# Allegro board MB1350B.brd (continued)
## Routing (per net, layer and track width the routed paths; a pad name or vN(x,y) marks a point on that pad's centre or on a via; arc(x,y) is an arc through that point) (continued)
VDD: length 42.2
  TOP w0.254: U8.5 30.49,83.17 C29.2 ; U1.8 51.93,142.86 52.2,143.13 52.2,143.76 C12.2 ; U19.3 v1(43.43,24.19) ; U10.1 81.93,67.93 C40.2 ; U11.1 93.33,67.93 v1(93.6,68.2) ; U11.5 96.89,66.43 C43.2 ; U8.1 37.58,81.67 R42.2
  TOP w0.508: C43.2 v1(97.16,65.15) ; R13.2 v1(51.05,145.8) ; C40.2 v1(81.15,69.6) ; L1.1 v1(75.18,79.76) R84.2 ; v1(39.87,83.78) 39.84,83.78 R40.2 ; R106.1 v1(86.23,23.67) ; R56.2 v1(82.8,65.28) ; R109.2 v1(60.58,17.53) ; R57.2 v1(95,64.39) ; C12.2 v1(53.09,145.8) ; R14.1 v1(69.34,145.8) ; CN13.1 v1(86.11,76.71) ; C29.2 v1(30.48,84.2) ; R105.1 v1(42.93,21.97) ; R53.2 v1(101.85,71.37) ; R42.2 v1(37.59,80.77) ; R49.2 96.14,76.2 v1(96.14,75.76) ; T2.1 v1(93.09,56.96)
  BOTTOM w0.508: v1(95,64.39) 95,63.75 93.85,62.61 93.85,58.42 93.09,57.66 v1(93.09,56.96)
VDD_ADJ: length 15.2
  TOP w0.508: 64.08,55.5 C56.1 ; C56.1 64.9,56.25 ; C56.1 65.71,55.5 ; 53.92,65.53 TP6.1 ; TP6.1 54.86,66.47 ; TP6.1 55.8,65.53 ; TP6.1 54.86,64.59 ; R65.1 61.47,58.88 ; R65.1 61.47,57.71 ; R65.1 62.04,58.29 ; C55.1 63.12,56.12 ; C55.1 63.7,55.5 ; C55.1 62.53,55.5 ; 61.47,56.31 C53.2 ; C53.2 62.09,56.9 ; C53.2 61.47,57.48 ; 61.92,66.42 JP16.3 ; JP16.3 63.81,66.42 ; JP16.3 62.87,65.48 ; 61.68,55.54 U14.4 61.27,56.07
VDD_ANA: length 211.2
  TOP w0.254: 72.34,40.34 U17.1 71.87,40.63 72.14,40.89
  TOP w0.508: JP13.1 51.18,71.5 49.15,73.53 45.97,73.53 41.4,78.11 41.4,109.22 v1(38.86,111.76) ; RV3.1 100.08,9.27 C91.2 103.38,14.61 JP18.2 ; 72.69,40.64 C74.2 ; C74.2 73.28,41.26 ; C74.2 73.86,40.64 ; 75.31,40.08 C75.1 ; C75.1 75.31,41.71 ; C75.1 74.37,40.89 ; C75.1 76.25,40.89 ; R66.1 v1(69.72,60.07) ; v1(84.96,60.07) C50.2 83.89,60.13 U12.5 ; R74.2 v1(78.36,55.63)
  BOTTOM w0.508: CN4.16 38.86,121.67 v1(38.86,111.76) ; JP13.1 66.42,60.07 v1(69.72,60.07) v1(84.96,60.07) 85.47,59.56 85.47,57.66 83.44,55.63 v1(78.36,55.63) 76.71,53.98 v1(76.71,41.66) ; v1(76.71,40.51) 70.1,40.51 67.39,37.8 67.39,27.48 69.72,25.15 81.79,25.15 82.55,24.38 82.55,20.83 88.52,14.86 JP18.2
VDD_MCU: length 59.4
  TOP w0.254: U7.8 55,86.48 v1(55.37,86.11)
  TOP w0.508: v1(68.96,92.33) 68.96,90.68 65.28,87 v1(65.28,86.61) 65.28,83.69 C31.1 68.71,83.44 69.34,84.07 JP11.1 ; SB13.2 52.83,104.9 v1(54.36,103.38)
  BOTTOM w0.508: v1(68.96,92.33) 68.45,92.33 59.69,101.09 56.64,101.09 v1(54.36,103.38) ; C32.2 C33.1 54.86,87.63 54.86,86.61 v1(55.37,86.11) 61.47,86.11 61.98,86.61 v1(65.28,86.61)
VDD_PG: length 2.6
  TOP w0.381: U14.3 61.27,51.63 R79.2
AIN_1: length 7.7
  TOP w0.127: R15.2 R14.2 68.83,143 67.82,141.99 67.82,138.68 67.54,138.4 U2.10
BOOTLOADER_BOOT0: length 67.3
  TOP w0.127: v1(65.53,88.9) 64.52,87.88 64.52,68.71 63.63,67.82 52.7,67.82 50.8,65.91 50.8,58.17 49.28,56.64 44.2,56.64 43.49,57.34 U13.20 ; D4.1 77.49,87.5 v1(78.23,87.5)
  BOTTOM w0.127: v1(65.53,88.9) 65.91,88.9 67.31,87.5 v1(78.23,87.5)
BOOTLOADER_RESET: length 18.5
  TOP w0.127: v1(44.81,55.98) SB28.2 44.79,54.74 U13.16
  BOTTOM w0.127: JP12.2 42.93,67.56 42.93,57.15 44.07,56.01 44.78,56.01 v1(44.81,55.98)
E5V: length 112.5
  TOP w0.508: L2.3 5.27,42.12 ; L2.3 4.1,43.29 ; L2.3 2.93,42.12 ; L2.3 4.1,40.96 ; 15.88,41.35 C70.1 ; C70.1 13.16,43.05 ; C70.1 15.88,44.76
  TOP w0.762: D10.1 40.53,114.94 34.92,114.94 24.26,104.27 24.26,89.03 23.09,87.86 21.74,87.86 20.98,87.1 20.98,83.31 20.5,82.83 15.82,82.83 v1(13.94,80.95) v1(13.94,79.98) ; 14.88,46.41 14.88,47.09 14.5,47.47 12.19,47.47 11.51,48.16 v1(11.51,50.6) 11.51,50.75 v1(12.19,51.44)
  TOP w1.016: JP17.6 5.33,45.21 5.46,45.09
  BOTTOM w0.762: v1(11.51,50.6) 11.51,50.77 12.17,51.44 v1(12.19,51.44) 12.75,51.44 14.55,53.24 14.55,62.05 13.94,62.66 v1(13.94,79.98) v1(13.94,80.95)
EXT_I2C_PWR: length 167.5
  TOP w0.508: CN2.5 9.64,151.5 8.89,150.75 R12.2 v1(9.91,146.56)
  BOTTOM w0.508: CN5.17 102.11,125.48 102.11,163.83 95.33,170.61 24.69,170.61 22.99,168.91 22.99,150.88 18.67,146.56 v1(9.91,146.56)
I2C_PU: length 49
  TOP w0.127: R9.2 R10.2 16.51,153.92 v1(26.42,153.92)
  BOTTOM w0.127: CN4.17 36.32,122.17 34.8,123.7 34.8,131.88 30.35,136.32 30.35,149.99 v1(26.42,153.92)
LED_STLINK: length 69.4
  TOP w0.127: v1(28.42,138.84) 29.21,138.05 51.69,138.05 52.84,136.9 U2.30 ; v1(11.43,113.49) 11.43,109.98 R35.1 R36.1
  BOTTOM w0.127: v1(28.42,138.84) 28.42,131.17 11.43,114.17 v1(11.43,113.49)
NETB2_2: length 18.5
  TOP w0.127: B2.3 66.87,9.97 66.55,10.29 C89.2 63.4,14.73 D9.1 60.6,14.71 R109.1 SB42.2 59.05,10.04 B2.2
NETB3_1: length 22.9
  TOP w0.127: B3.1 75.62,7.63 75.62,9.86 77.85,12.09 79.5,12.09 80.92,13.51 80.92,14.33 80.71,14.54 D8.4 80.03,14.54 79.73,14.25 v1(79.73,13.64) ; SB39.2 C85.2 v1(78.49,19.43)
  BOTTOM w0.127: v1(78.49,19.43) 78.49,14.88 v1(79.73,13.64)
NETB3_2: length 25
  TOP w0.127: B3.2 77.5,5.11 76.1,5.11 74.85,6.35 74.85,10.13 77.44,12.73 78.56,12.73 79.1,13.26 79.1,15.7 78.35,16.44 D8.1 76.14,16.44 75.31,17.27 C84.2 SB38.2
NETB3_3: length 28.8
  TOP w0.127: B3.3 78.48,4.11 76,4.11 74.12,5.99 74.12,10.31 77.14,13.34 78.26,13.34 78.51,13.59 78.51,14.33 78.29,14.54 D8.3 75.85,14.54 72.14,18.26 C83.2 SB37.2
NETB3_4: length 20.9
  TOP w0.127: SB40.2 C86.2 81.66,19.94 79.15,17.42 79.15,16.26 79.91,15.49 D8.5 80.75,15.49 81.53,14.71 81.53,13.03 79.4,10.9 79.4,10.11 81.61,7.9 82.27,7.9 B3.4
NETB3_5: length 12.8
  TOP w0.127: B3.5 86.23,13.84 R106.2
NETB3_6: length 15.8
  TOP w0.127: SB41.2 C87.2 84.71,20.19 83.82,19.3 82.22,19.3 80.32,17.41 D8.6 80.76,16.44 82.12,15.09 82.12,11.71 B3.6
NETBT1_1: length 29.6
  TOP w0.508: BT1.1 v1(50.62,39.83)
  BOTTOM w0.508: v1(50.62,39.83) 50.62,63.42 JP15.3
NETC5_2: length 55.2
  TOP w0.127: R1.1 R2.2 C5.2 v1(57.02,158.75)
  BOTTOM w0.127: v1(57.02,158.75) 58.42,160.15 58.42,167.64 57.2,168.86 31.57,168.86 25.91,163.19 25.91,158.5 JP3.1
NETC6_2: length 52.2
  TOP w0.127: v1(60.45,157.99) C6.2 R3.2
  BOTTOM w0.127: v1(60.45,157.99) 60.96,158.5 60.96,167.51 59.13,169.34 31.29,169.34 JP2.2
NETC10_2: length 61.7
  TOP w0.127: v1(72.52,158.75) R7.2 R8.2 C10.2
  BOTTOM w0.127: v1(72.52,158.75) 71.12,160.15 71.12,167.77 69.01,169.88 26.49,169.88 JP1.2
NETC11_2: length 1.8
  TOP w0.127: C11.2 SB1.1
NETC24_2: length 2.3
  TOP w0.508: C24.2 47.3,123.5 U4.4
NETC26_2: length 13.1
  TOP w0.508: 47.8,118.94 U4.3 47.3,118.19 ; D10.2 43.29,116.03 ; D10.2 43.87,115.44 ; D10.2 42.7,115.44 ; D10.2 43.29,114.86 ; D3.2 43.29,114 ; D3.2 43.87,113.41 ; D3.2 42.7,113.41 ; D3.2 43.29,112.83 ; D2.2 43.87,117.47 ; D2.2 43.29,118.06 ; D2.2 42.7,117.47 ; D2.2 43.29,116.89 ; C26.2 45.47,117.84 ; C26.2 44.88,117.22 ; C26.2 46.05,117.22 ; C27.2 47.57,117.22 ; C27.2 46.99,117.84 ; C27.2 46.41,117.22 ; 45.41,118.19 U4.1 44.91,118.94
NETC34_1: length 4.3
  TOP w0.127: R43.1 50.42,80.01 C34.1 49.78,77.6 X2.2
NETC35_1: length 4.4
  TOP w0.127: X2.1 50.93,77.73 50.93,79.12 C35.1 51.69,79.88 R44.1
NETC36_1: length 4.4
  TOP w0.127: X3.2 58.8,77.1 C36.1 58.93,79.5 R45.1
NETC37_1: length 4.4
  TOP w0.127: R46.1 60.2,79.5 C37.1 60.33,77.1 X3.1
NETC44_1: length 4.4
  TOP w0.127: U13.3 33.89,61.24 33.25,60.6 32.11,60.6 C44.1
NETC45_1: length 2.6
  TOP w0.127: U13.1 33.09,62.54 C45.1
NETC45_2: length 2.6
  TOP w0.127: U13.2 33.27,61.89 C45.2
NETC46_1: length 6.6
  TOP w0.508: TP9.1 C46.1 R62.1 R61.2
NETC47_1: length 10.1
  TOP w0.254: U12.4 82.48,58.23 83.31,57.4 R70.1 83.31,55.09 RV1.1
  TOP w0.508: U12.4 81.59,58.23 80.9,58.93 80.9,60.83 81.28,61.21 C47.1 R59.2
NETC47_2: length 5
  TOP w0.508: R62.2 79.64,60.07 U12.1 79.76,60.19 C47.2 R59.1
NETC48_1: length 2.7
  TOP w0.127: U13.27 44.82,61.89 C48.1
NETC49_1: length 4.7
  TOP w0.127: C49.1 45.31,59.46 44.04,59.46 43.56,59.94 U13.24
NETC49_2: length 4.5
  TOP w0.127: C49.2 45.57,62.76 43.15,62.76 42.93,62.54 U13.28
NETC51_1: length 5.1
  TOP w0.254: C51.1 C54.1 75.44,55.88 R72.1 R73.1
NETC51_2: length 13.4
  TOP w0.508: TP8.1 72.9,59.94 R68.2 75.31,59.05 76.83,59.05 C51.2 79.63,58.17 U12.3
NETC53_1: length 4.6
  TOP w0.381: U14.5 60.33,56.52 C53.1
  TOP w0.508: R64.1 R65.2 C53.1
NETC58_1: length 11.8
  TOP w0.254: RV1.2 85.35,51.98 RV1.3 84.84,55.35 R70.2 87.5,56.77 88.27,56.01 C58.1
NETC59_1: length 5.8
  TOP w0.254: R67.1 R66.2 R69.1 71.25,54.86 C59.1
NETC60_1: length 4.2
  TOP w0.254: C60.1 72.9,54.74 R67.2 R68.1
NETC61_1: length 3.9
  TOP w0.254: C61.1 79.12,53.21 R74.1 R73.2
NETC62_1: length 3.9
  TOP w0.381: C62.1 59.38,50.61 U14.1
  TOP w0.508: R80.1 C62.1
NETC63_1: length 7.5
  TOP w0.127: SB30.2 51.21,50.57 50.83,50.19 47.14,50.19 R82.1 C63.1
NETC63_2: length 63.4
  TOP w0.127: CN11.4 14.71,74.7 17.78,71.63 17.78,66.67 19.11,65.35 24.06,65.35 26.48,62.92 26.48,59.37 28.96,56.9 28.96,49.1 31.83,46.23 37.72,46.23 40.41,48.92 U15.6 42.82,48.92 C63.2 44.48,50.57 47.9,50.57 48.03,50.7 SB29.2 SB30.1
NETC65_2: length 75.7
  TOP w0.127: C65.2 69.85,49.3 68.22,50.93 68.22,65.71 78.44,75.92 78.44,82.73 74.75,86.41 73.23,86.41 70.36,89.28 70.36,94.16 72.86,96.66 76.24,96.66 79.63,100.05 JP19.1
  TOP w0.381: C66.1 C65.2
NETC66_2: length 1.5
  TOP w0.381: R89.1 C66.2
NETC67_1: length 4.7
  TOP w0.508: U16.5 C67.1 R88.2 R87.1
NETC68_1: length 11.4
  TOP w0.254: U17.2 71.37,40.89 C73.2
  TOP w0.381: C68.1 73.41,44.45 R90.2 C73.2
NETC68_2: length 19.7
  TOP w0.381: CN15.6 100.96,46.1 R86.2 96.14,46.1 94.23,44.2 94.23,42.29 92.9,40.95 D6.6 89.14,44.45 C68.2
NETC69_1: length 2.7
  TOP w0.254: C69.1 70.37,41.01 U17.4
NETC73_1: length 5.6
  TOP w0.254: C73.1 70.87,41.91 U17.3
  TOP w0.381: R89.2 R90.1 C73.1
NETC76_1: length 5.1
  TOP w0.254: U17.7 71.37,36.83 C76.1
  TOP w0.381: R95.2 R94.1 C76.1
NETC76_2: length 11.3
  TOP w0.254: U17.8 71.87,38.19 71.88,38.18 71.88,37.34 C76.2
  TOP w0.381: C77.1 77.09,35.56 76.45,34.92 R94.2 C76.2
NETC77_2: length 24.4
  TOP w0.381: C77.2 88.77,35.56 92.27,39.06 D6.4 94.29,39.06 95.63,37.72 R92.2 108.36,37.72 CN15.4
NETC78_2: length 4
  TOP w0.381: C80.1 70.36,32.77 69.98,32.77 C78.2 R93.2
NETC79_1: length 18.3
  TOP w0.508: D7.1 15.23,35.88 ; D7.1 15.23,34.73 ; D7.1 15.69,35.31 ; 15.11,29.96 U18.3 ; U18.3 15.76,30.45 ; U18.3 15.11,30.93 ; 15.24,31.93 C79.1 ; C79.1 15.24,33.1 ; C79.1 15.86,32.51
  TOP w1.143: 15.62,38.1 13.97,39.75 9.14,39.75 6.52,37.12 L2.1
NETC79_2: length 23.5
  TOP w0.508: 9.4,38.35 9.1,38.06 L2.2 ; CN16.2 7.54,23.12 ; CN16.2 9.83,21.92 ; CN16.2 7.54,20.73 ; CN16.2 5.26,21.92 ; CN16.3 5.64,26.92 ; CN16.3 4.45,24.64 ; CN16.3 4.45,29.21 ; CN16.3 3.25,26.92 ; C79.2 13.72,33.1 ; C79.2 13.09,32.51 ; C79.2 13.72,31.93 ; L2.2 10.27,37.12 ; L2.2 8.17,37.12 7.87,36.83 ; L2.2 9.1,35.95 ; D7.2 13.98,35.88 ; D7.2 13.98,34.73 ; D7.2 13.52,35.31 ; 13.19,30.45 U18.2 13.84,30.93
NETC80_2: length 1.4
  TOP w0.381: C80.2 R95.1
NETC81_1: length 10.2
  TOP w0.508: L3.2 89.79,29.34 C82.1 92.33,28.96 C81.1 95.5,30.48 CN14.13 CN14.14
NETC81_2: length 10
  TOP w0.508: L4.2 91.82,26.42 C82.2 92.84,27.43 C81.2 96.01,27.43 CN14.15 CN14.16
NETC89_1: length 1.7
  TOP w0.127: C89.1 R110.2
NETC90_2: length 3.2
  TOP w0.127: SB43.2 C90.2 R111.1
NETC93_1: length 3.9
  TOP w0.381: C93.1 59.38,26.99 U21.1
  TOP w0.508: C93.1 R115.1
NETC94_1: length 4.7
  TOP w0.508: U21.5 C94.1 R116.2 R117.1
NETCN1_1: length 42.8
  TOP w0.127: CN1.1 87.63,167.94 86.41,169.16 57.4,169.16 55.93,167.69 55.93,161.59 54.86,160.53 R2.1
NETCN1_14: length 4.9
  TOP w0.127: CN1.14 72.39,160.4 R7.1
NETCN1_15: length 7.8
  TOP w0.127: CN1.15 70.87,165.61 70.87,162.69 71.63,161.93 R6.2
NETCN1_17: length 7.7
  TOP w0.127: CN1.17 68.58,165.35 68.58,162.69 68.83,162.43 R5.2
NETCN1_19: length 7.6
  TOP w0.127: CN1.19 65.91,165.48 R4.2
NETCN1_26: length 4.8
  TOP w0.127: R3.1 57.78,163.45 CN1.26
NETCN4_6: length 3.6
  TOP w0.127: R11.2 CN4.6
NETCN6_4: length 3.9
  TOP w0.127: R19.1 5.73,134.86 CN6.4
NETCN8_2: length 8.3
  TOP w0.127: U6.13 95.18,103.56 95,103.38 94.49,103.38 v1(93.92,103.95) ; v1(97.54,101.73) 99.07,101.73 CN8.2
  BOTTOM w0.127: v1(93.92,103.95) 94.49,103.38 95.63,103.38 97.28,101.73 v1(97.54,101.73)
NETCN8_3: length 5.7
  TOP w0.127: CN8.3 v1(97.54,102.99) ; v1(94.74,103.96) U6.12
  BOTTOM w0.127: v1(94.74,103.96) 95.69,103.96 96.52,103.12 97.41,103.12 97.54,103 v1(97.54,102.99)
NETCN8_5: length 11.5
  TOP w0.127: CN8.5 v1(100.68,105.19) ; U6.11 95.16,104.36 94.87,104.65 94.49,104.65 v1(93.98,105.16)
  BOTTOM w0.127: v1(100.68,105.19) 99.44,106.43 97.03,106.43 95.25,104.65 94.49,104.65 v1(93.98,105.16)
NETCN8_7: length 9.4
  TOP w0.127: v1(100.71,107.39) CN8.7 ; U6.10 95.36,104.76 94.97,105.16 v1(94.74,105.16)
  BOTTOM w0.127: v1(100.71,107.39) 99.13,107.39 98.55,106.81 96.77,106.81 95.12,105.16 v1(94.74,105.16)
NETCN8_10: length 26.1
  TOP w0.127: SB8.2 109.73,110.84 CN8.10 109.43,103.33 107.31,101.22 102.11,101.22 100.84,99.95 98.04,99.95 97.03,100.97 97.03,102.23 96.9,102.36 U6.1
NETCN9_18: length 36.3
  TOP w0.127: SB19.1 53.72,81.66 53.72,83.31 52.83,84.2 v1(52.83,85.34)
  BOTTOM w0.127: CN9.18 51.56,86.61 v1(52.83,85.34)
NETCN9_19: length 32.5
  TOP w0.127: SB18.2 v1(47.5,80.9)
  BOTTOM w0.127: v1(47.5,80.9) 43.18,85.22 29.21,85.22 28.32,86.11 23.75,86.11 22.86,85.22 20.83,85.22 CN9.19
NETCN9_21: length 29.8
  TOP w0.127: R47.1 v1(45.21,80.64)
  BOTTOM w0.127: v1(45.21,80.64) 43.05,82.8 28.96,82.8 27.05,84.71 24.38,84.71 22.48,82.8 20.95,82.8 CN9.21
NETCN10_13: length 33.4
  TOP w0.127: v1(60.96,85.22) 61.59,84.58 SB21.2
  BOTTOM w0.127: v1(60.96,85.22) 62.23,85.22 62.99,85.98 66.04,85.98 66.42,85.6 79.6,85.6 85.7,91.69 CN10.13
NETCN10_15: length 36.3
  TOP w0.127: v1(58.8,84.85) 57.53,83.58 SB20.2
  BOTTOM w0.127: v1(58.8,84.85) 58.92,84.85 59.05,84.71 65.53,84.71 67.94,82.3 79.25,82.3 86.11,89.15 CN10.15
NETCN10_18: length 9.7
  TOP w0.127: R41.2 88.77,82.93 89.53,83.69 89.53,85.34 CN10.18
NETCN10_19: length 15.4
  TOP w0.127: R39.1 77.47,85.22 85.47,85.22 86.61,84.07 CN10.19
NETCN10_20: length 7.6
  BOTTOM w0.127: CN10.20 89.79,83.06 83.82,83.06 SB44.1
NETCN10_22: length 8.1
  BOTTOM w0.127: CN10.22 89.66,82.68 87.38,82.68 86.11,81.41 SB45.1
NETCN11_2: length 37.6
  TOP w0.127: U13.6 34.09,59.29 34.07,59.27 30.81,59.27 29.11,60.97 29.11,67.79 22.35,74.55 17.53,74.55 11.84,80.24 CN11.2
NETCN11_3: length 37.6
  TOP w0.127: U13.10 30.89,56.69 27.57,60.01 27.57,67.05 21.46,73.15 16.89,73.15 12.57,77.47 CN11.3
NETCN11_6: length 40.7
  TOP w0.127: CN11.6 11.07,81.64 17.53,75.18 22.48,75.18 29.68,67.98 29.68,61.12 30.89,59.92 34.07,59.92 34.09,59.94 U13.5
NETCN11_7: length 40.6
  TOP w0.127: CN11.7 7.75,78.61 12.19,78.61 17.14,73.66 21.72,73.66 28.09,67.28 28.09,60.38 31.12,57.34 U13.9
NETCN11_8: length 46.4
  TOP w0.127: U13.7 34.09,58.64 34.07,58.62 30.61,58.62 28.6,60.62 28.6,67.54 22.1,74.04 17.4,74.04 12.45,78.99 9.4,78.99 8.13,80.26 6.86,80.26 6.1,79.5 6.1,77.5 CN11.8
NETCN11_9: length 69.8
  TOP w0.127: SB32.2 SB31.2 48.03,46.76 47.65,46.38 42.6,46.38 v1(42.57,46.35) 38.61,46.35 37.97,45.72 31.5,45.72 28.45,48.77 28.45,56.64 26.04,59.05 26.04,62.74 23.88,64.9 18.92,64.9 17.14,66.67 17.14,71.5 15.32,73.33 CN11.9 ; v1(42.57,50.19) U15.7
  BOTTOM w0.127: v1(42.57,46.35) v1(42.57,50.19)
NETCN12_7: length 19.4
  TOP w0.127: CN13.2 94.87,76.71 R49.1 R48.1 95,78.99 95.58,79.58 101.82,79.58 U9.3 107.27,78.12 108.01,78.87
NETCN12_9: length 17.3
  TOP w0.127: CN12.9 107.52,76.82 U9.1 102.88,76.82 102.49,77.22 99.95,77.22 97.66,74.93 R51.2 R50.1 94.49,75.44 CN13.4
NETCN12_11: length 6.1
  TOP w0.127: 108.01,73.79 103.5,73.79 R52.2 R53.1
NETCN12_15: length 27.8
  TOP w0.127: CN13.10 94.87,71.63 R54.1 96.01,72.52 97.79,72.52 98.81,73.53 98.81,75.31 100.32,76.82 U9.5 101.74,76.82 103.38,75.18 108.71,75.18 109.35,74.55 109.35,70.04 CN12.15
NETCN12_17: length 4.3
  TOP w0.127: R55.2 CN12.17
NETCN12_19: length 4.3
  TOP w0.127: R58.2 108.01,63.63
NETCN14_1: length 4.6
  TOP w0.254: 93.73,60.07 R60.1 95.89,61.59 CN14.1
NETCN14_3: length 2.8
  TOP w0.254: R63.1 CN14.3
NETCN14_7: length 3.3
  TOP w0.127: CN14.7 95.38,52.2 R76.2
NETCN14_8: length 8.7
  TOP w0.127: T2.3 94.19,55.08 93.73,54.61 R75.1 94.23,53.59 95,54.36 98.04,54.36 CN14.8
NETCN15_2: length 55.9
  TOP w0.254: v1(89.41,48.13) 88.61,48.13 87.59,49.15 76.43,49.15 75.44,50.14 R72.2 ; CN15.2 v1(113.25,47.66) ; D6.1 v1(88.83,40.95)
  BOTTOM w0.254: v1(113.25,47.66) 111.3,45.72 100.33,45.72 95.56,40.95 v1(88.83,40.95) 88.52,41.27 88.52,47.24 v1(89.41,48.13)
NETCN16_1: length 10.5
  TOP w0.508: CN16.1 11.84,26.92 ; CN16.1 10.64,29.21 ; CN16.1 10.64,24.64 ; CN16.1 9.45,26.92 ; U18.1 14.48,27.44 ; U18.1 15.76,26.96 ; U18.1 13.19,26.96 ; U18.1 14.48,26.47
NETCN17_1: length 14.9
  TOP w0.127: R111.2 R112.1 95.5,17.78 96.27,18.54 105.41,18.54 CN17.1
NETD1_2: length 2.6
  TOP w0.127: R28.1 65.77,124.1 D1.2
NETD4_2: length 2.9
  TOP w0.127: D4.2 JP9.3
NETD5_2: length 24.5
  TOP w0.127: D5.2 58.66,70.23 42.8,70.23 JP12.1
NETJP4_2: length 65.4
  TOP w0.127: R61.1 74.55,71.04 79.12,75.62 79.12,82.83 74.83,87.12 73.41,87.12 70.87,89.66 70.87,93.98 72.73,95.85 76.87,95.85 80.85,99.82 80.85,107.14 80.31,107.67 76.17,107.67 JP4.2
NETJP5_2: length 90
  TOP w0.127: R27.1 62.74,126.36 62.23,125.86 62.23,124.97 61.47,124.21 50.8,124.21 44.7,130.3 31.37,130.3 v1(30.86,129.79) ; R27.1 62.23,127.51 62.23,129.79 60.73,131.29 U2.39 ; R27.1 R28.2
  BOTTOM w0.127: v1(30.86,129.79) 31.59,129.06 31.59,112.49 28.7,109.6 18.41,109.6 12.06,103.25 JP5.2
NETJP6_2: length 74.1
  TOP w0.127: R93.1 67.56,38.35 67.56,66.14 77.75,76.33 77.75,82.3 74.3,85.75 73.1,85.75 69.82,89.03 69.82,94.34 74.55,99.06 JP6.2
NETJP8_2: length 39.4
  BOTTOM w0.127: JP14.2 17.86,70.79 17.86,91.82 19.2,93.17 29.92,93.17 JP8.2
NETJP10_2: length 13.7
  TOP w0.127: JP10.2 34.54,88.14 34.54,82.8 35.17,82.17 U8.2 36.71,82.17 36.83,82.3 38.48,82.3 R42.1
NETJP11_2: length 3.3
  TOP w0.508: R84.1 JP11.2
NETJP14_1: length 33.1
  TOP w0.127: U13.17 v1(40.64,55.39) ; v1(26.42,64.77) JP14.1
  BOTTOM w0.127: v1(40.64,55.39) 29.19,55.39 26.42,58.17 v1(26.42,64.77)
NETJP14_3: length 39.3
  TOP w0.127: U15.1 37.57,51.46 37.85,51.18 37.85,47.24 37.34,46.74 32,46.74 29.46,49.28 29.46,57.18 26.95,59.69 26.95,63.22 23.75,66.42 JP14.3
NETJP18_1: length 57.8
  TOP w0.127: R108.1 99.82,17.4 JP18.1 ; v1(70.23,37.34) 70.87,37.98 U17.6
  BOTTOM w0.127: JP18.1 100.43,17.4 99.54,16.51 87.76,16.51 83.19,21.08 83.19,24.89 82.17,25.91 71.37,25.91 70.03,27.25 70.03,37.13 v1(70.23,37.34)
NETL3_1: length 4.1
  TOP w0.508: R100.2 R96.2 86.74,28.07 L3.1
NETLD1_2: length 19.7
  TOP w0.127: LD1.2 19.94,10.79 29.72,20.57 R104.2
NETLD2_2: length 19.7
  TOP w0.127: R103.2 28.07,20.32 18.16,10.41 LD2.2
NETLD3_2: length 19.8
  TOP w0.127: R102.2 26.42,20.19 16.38,10.16 LD3.2
NETLD4_2: length 19.8
  TOP w0.127: R101.2 24.77,19.94 14.61,9.78 LD4.2
NETLD5_1: length 1.5
  TOP w0.127: R33.2 LD5.1
NETLD5_2: length 23.8
  TOP w0.127: v1(10.72,111.76) 9.68,110.72 6.5,110.72 LD5.2 ; U5.3 22.87,120.65 R31.2 v1(20.95,121.79)
  BOTTOM w0.127: v1(20.95,121.79) 20.75,121.79 v1(10.72,111.76)
NETLD6_2: length 3.6
  TOP w0.127: LD6.2 8.09,108.17 R35.2
NETLD6_3: length 3.6
  TOP w0.127: LD6.3 7.99,106.67 R36.2
NETLD6_4: length 6.8
  TOP w0.127: R37.1 8.51,105.66 3.46,105.66 LD6.4
NETLD7_1: length 1.8
  TOP w0.508: R71.1 LD7.1
NETLD8_2: length 1.5
  TOP w0.127: LD8.2 R83.1
NETR13_1: length 5.9
  TOP w0.127: R13.1 49.53,143.41 51.08,141.86 U1.6 52.83,141.86 SB5.1
NETR16_2: length 2.6
  TOP w0.127: R16.2 61.47,142.91 61.73,142.65 U2.20
NETR18_2: length 1.7
  TOP w0.127: T1.2 11.68,131.68 R18.2
NETR20_2: length 4.6
  TOP w0.127: T1.1 13.4,129.73 R20.2 R21.1 R22.1
NETR23_2: length 2.4
  TOP w0.127: U2.44 63.23,130.06 R23.2
NETR24_2: length 6.7
  TOP w0.127: R24.2 68.71,131.95 68.71,133.6 67.91,134.4 U2.2
NETR25_2: length 7.1
  TOP w0.127: U2.3 68.04,134.9 69.22,133.73 69.22,131.06 R25.2
NETR34_1: length 8.6
  TOP w0.127: U6.4 96.77,103.5 97.92,103.5 98.17,103.76 98.17,107.57 97.66,108.08 97.28,108.08 SB9.2 R34.1
NETR38_1: length 4.4
  TOP w0.127: R38.1 49.34,94.23 U7.57
NETR40_1: length 3.9
  TOP w0.127: U8.3 36.19,82.67 36.58,83.06 R40.1 SB16.2
NETR56_1: length 4.2
  TOP w0.127: SB26.2 R56.1 85.34,66.29 85.48,66.43 U10.5
NETR57_1: length 5.6
  TOP w0.127: R57.1 94.23,66.04 94.23,67.06 93.86,67.43 U11.2 91.82,67.43 SB25.2
NETR64_2: length 68
  TOP w0.127: RV2.1 39.37,18.8 48.13,18.8 49.91,20.57 49.91,29.21 53.59,32.89 53.59,57.28 54.61,58.29 R64.2
NETR76_1: length 63.8
  TOP w0.127: SB12.2 97.41,106.43 97.41,106.05 v1(97.17,105.8) 97.17,104.91 97.01,104.76 U6.7 ; v1(91.31,52.2) R76.1 R78.2
  BOTTOM w0.127: v1(97.17,105.8) 97.17,105.02 97.46,104.73 98.6,104.73 99.54,103.78 99.54,70.84 98.04,69.34 98.04,68.45 96.65,67.06 96.65,63.75 95,62.1 95,57.66 92.33,54.99 92.33,53.21 v1(91.31,52.2)
NETR77_1: length 1.5
  TOP w0.127: R77.1 SB29.1
NETR82_2: length 4.8
  TOP w0.127: R82.2 50.7,49.56 51.21,49.05 SB32.1
NETR83_2: length 45
  TOP w0.127: R83.2 v1(16,48.51) ; v1(40.51,25.49) U19.1
  BOTTOM w0.127: v1(40.51,25.49) 35.6,25.49 28.19,32.89 28.19,47.12 26.8,48.51 v1(16,48.51)
NETR85_1: length 1.5
  TOP w0.127: SB31.1 R85.1
NETR97_1: length 1.9
  TOP w0.127: R98.1 R97.1
NETR97_2: length 5.6
  TOP w0.127: R97.2 R99.1 43.94,25.27 43.51,24.84 U19.2
NETR101_1: length 1.4
  TOP w0.127: R101.1 SB33.1
NETR102_1: length 1.4
  TOP w0.127: R102.1 SB34.1
NETR103_1: length 1.4
  TOP w0.127: SB35.1 R103.1
NETR104_1: length 1.4
  TOP w0.127: SB36.1 R104.1
NETR105_2: length 4.3
  TOP w0.127: R105.2 45.59,23.88 45.9,24.19 U19.6
NETR107_2: length 4.8
  TOP w0.127: R107.2 47.12,20.57 47.83,21.29 U19.5
NETR112_2: length 1.5
  TOP w0.127: R113.1 R112.2
NETR113_2: length 8.9
  TOP w0.127: R113.2 RV3.2
NETSB4_1: length 1.9
  TOP w0.127: U1.7 52.7,142.36 SB4.1
NETSB10_1: length 7.3
  TOP w0.127: SB10.1 SB13.1 55,104.9 U7.41
NETSB11_1: length 7.3
  TOP w0.127: SB11.1 SB14.1 55.49,105.02 U7.40
NETSB15_1: length 1.7
  TOP w0.127: U6.16 95.56,100.77 SB15.1
NETSB24_2: length 1.9
  TOP w0.127: SB24.2 81.4,67.43 U10.2
NETTP2_1: length 77.5
  TOP w0.127: U2.21 61.23,142.22 60.58,142.88 60.58,146.05 58.04,148.59 47.62,148.59 39.88,140.84 29.57,140.84 v1(27.58,138.86)
  BOTTOM w0.127: TP2.1 27.58,131.24 v1(27.58,138.86)
OSC_IN: length 7.8
  TOP w0.127: U2.5 68.57,135.9 C19.1 69.85,135.89 73.02,135.89 X1.2
OSC_OUT: length 7.5
  TOP w0.127: U2.6 68.84,136.4 C18.1 69.98,137.54 73.67,137.54 X1.1
PA0: length 122.7
  TOP w0.127: v1(74.42,26.42) 73.79,25.78 SB38.1 ; v1(62.48,90.17) 61.92,90.74 U7.17
  BOTTOM w0.127: v1(74.42,26.42) 74.55,26.54 82.3,26.54 82.55,26.8 82.55,27.56 83.82,28.83 83.82,30.35 84.2,30.73 84.2,53.34 89.36,58.5 89.36,64.34 90.81,65.79 90.81,69.18 93.4,71.78 93.4,93.9 92.02,95.28 89.89,95.28 88.39,96.77 CN10.9 87.35,96.75 78.61,88.01 67.69,88.01 64.96,90.74 63.05,90.74 v1(62.48,90.17)
PA1: length 112.1
  TOP w0.127: v1(68.96,115.7) 69.85,114.81 69.85,95.66 64.87,90.68 62.55,90.68 61.99,91.24 U7.18 ; JP1.1 30.48,168.15 CN4.1
  BOTTOM w0.127: v1(68.96,115.7) 68.71,115.95 56.08,115.95 48.29,123.75 48.29,129.01 36.45,140.84 35.69,140.84 34.72,141.81 34.72,160.71 CN4.1
PA2: length 120
  TOP w0.127: U7.19 62.19,91.74 62.61,91.31 64.59,91.31 69.22,95.94 69.22,113.8 68.33,114.69 68.33,116.2 68.63,116.51 89.33,116.51 v1(91.45,118.63) ; CN5.8 96.6,146.23 96.6,150.88 90.86,156.62 73,156.62 R6.1 C9.2
  BOTTOM w0.127: v1(91.45,118.63) 91.45,137.68 CN5.8
PA3: length 106.2
  TOP w0.127: v1(67.56,114.55) 67.56,112.12 68.58,111.1 68.58,96.22 64.6,92.24 U7.20
  BOTTOM w0.127: JP2.1 28.68,161.19 28.68,154.2 31.32,151.56 31.32,136.86 33.81,134.37 CN4.12 38.66,132.03 38.66,128.57 40.84,126.39 40.84,122.5 49.99,113.36 66.37,113.36 v1(67.56,114.55)
PA4: length 43.8
  TOP w0.127: v1(67.94,102.62) 67.94,96.49 64.41,92.96 63.07,92.96 62.85,92.74 U7.21
  BOTTOM w0.127: v1(67.94,102.62) 70.74,99.82 JP6.1 74.3,102.11 78.23,102.11 82.17,106.05 84.38,106.05 85.06,105.36 88.94,105.36 89.61,104.69 89.61,103.05 CN10.6
PA5: length 37.5
  TOP w0.127: U7.22 62.71,93.24 63.14,93.68 64.16,93.68 67.31,96.82 v1(67.31,101.7)
  BOTTOM w0.127: v1(67.31,101.7) 70.84,98.17 75.44,98.17 JP6.3 77.46,99.82 82.03,104.39 CN10.3
PA6: length 105
  TOP w0.127: U7.23 62.4,93.74 63.12,94.46 64.03,94.46 66.67,97.1 66.67,104.78 v1(67.94,106.05) ; v1(68.83,156.46) R5.1 C8.2
  BOTTOM w0.127: CN10.4 89.2,105.99 85.65,105.99 84.07,107.57 73.53,107.57 JP4.1 v1(67.94,106.05) 66.9,106.05 66.04,106.91 66.04,109.7 77.67,121.34 77.67,148.64 69.85,156.46 v1(68.83,156.46)
PA7: length 102.2
  TOP w0.127: v1(67.94,107.7) 66.04,105.79 66.04,97.38 63.75,95.1 62.86,95.1 62,94.24 U7.24 ; v1(95.07,70.03) 94.74,70.36 79.25,70.36 78.74,69.85 78.74,68.07 SB24.1
  BOTTOM w0.127: v1(67.94,107.7) 70,109.75 85.45,109.75 CN10.1 89.2,106.93 90.37,105.77 91.01,105.77 92.08,104.7 92.08,102.74 97.66,97.16 97.66,74.68 96.9,73.91 96.9,71.85 v1(95.07,70.03)
PA8: length 109
  TOP w0.127: v1(87.22,118.92) 86.41,118.11 62.74,118.11 60.2,115.57 60.2,104.27 57.49,101.56 U7.36 ; CN5.1 87.12,162.31 86.36,163.07 86.36,165.35 CN1.3
  BOTTOM w0.127: CN5.1 98.3,161.54 87.63,150.88 87.63,119.33 v1(87.22,118.92)
PA9: length 148.5
  TOP w0.127: CN1.7 78.74,165.35 78.74,162.61 81.61,159.74 95.78,159.74 CN5.3 ; v1(89.66,118.87) 88.99,119.54 86.87,119.54 85.81,118.49 62.48,118.49 59.75,115.76 59.75,104.36 57,101.6 U7.37 v1(57,94.23)
  BOTTOM w0.127: v1(57,94.23) 49.72,94.23 47.88,92.39 46.04,92.39 44.07,90.42 JP10.3 ; CN5.3 96.65,157.23 88.42,149 88.42,120.12 v1(89.66,118.87)
PA10: length 149.4
  TOP w0.127: v1(53.47,95.25) 53.59,95.38 53.59,97.92 54.49,98.82 U7.42 54.49,101.84 51.31,105.03 51.31,108.71 60.69,118.09 60.69,118.09 60.98,118.38 60.98,118.38 61.47,118.87 85.56,118.87 86.61,119.93 89.5,119.93 v1(89.66,119.76) ; CN1.11 76.2,165.35 76.2,162.31 76.71,161.8 78.66,161.8 81.23,159.23 93.75,159.23 CN5.4
  BOTTOM w0.127: JP8.3 41.27,95.38 43.18,93.47 47.62,93.47 49.4,95.25 v1(53.47,95.25) ; CN5.4 95.63,154.69 88.9,147.96 88.9,120.52 v1(89.66,119.76)
PA11: length 113.8
  TOP w0.127: U7.43 54,101.71 51.56,104.14 v1(51.31,104.14)
  TOP w0.155: SB28.1 v1(46.33,53.59)
  BOTTOM w0.127: v1(46.33,53.59) 45.95,53.98 27.86,53.98 23.62,58.21 23.62,61.51 21.08,64.05 18.41,64.05 16.89,65.58 16.89,100.84 19.18,103.12 20.19,103.12 21.46,104.39 CN9.4 22.48,104.14 v1(51.31,104.14)
PA12: length 54.8
  TOP w0.127: v1(51.31,103.25) 51.86,103.25 53.49,101.62 U7.44
  TOP w0.155: SB16.1 v1(39.12,103.25)
  BOTTOM w0.127: CN9.5 21.08,103.25 v1(39.12,103.25) v1(51.31,103.25)
PA13: length 140.1
  TOP w0.127: SB4.2 55.37,142.49 v1(56.01,142.49) ; U2.27 v1(56.92,138.4) ; v1(95.89,78.99) 96.52,78.36 R48.2 ; v1(60.36,118.49) 60.33,118.46 60.33,118.27 50.55,108.49 50.55,103.31 51.1,102.76 51.8,102.76 53,101.56 U7.45
  BOTTOM w0.127: v1(56.01,142.49) 55.37,141.86 55.37,140.59 56.92,139.04 v1(56.92,138.4) 56.92,138.2 53.09,134.37 53.09,123.57 56.29,120.37 58.48,120.37 v1(60.36,118.49) 68.37,118.49 69.72,117.15 69.72,115.44 64.31,110.03 64.31,103.71 70.74,97.28 77.6,97.28 83.06,102.74 87.38,102.74 CN10.5 88.77,101.85 90.32,100.3 91.52,100.3 95.89,95.94 v1(95.89,78.99)
PA14: length 30.9
  TOP w0.127: v1(71.88,89.79) 72.01,89.66 R39.2 JP9.2 ; U7.46 v1(52.49,98.91)
  BOTTOM w0.127: v1(52.49,98.91) 52.62,99.03 59.21,99.03 68.45,89.79 v1(71.88,89.79)
PA15: length 75.3
  TOP w0.127: U7.47 52,101.93 51.55,102.37 50.94,102.37 50.16,103.15 50.16,108.97 v1(59.63,118.43)
  BOTTOM w0.127: CN4.2 36.32,159.13 40.51,154.94 40.51,141.1 50.57,131.04 50.57,125.45 56.06,119.96 58.09,119.96 v1(59.63,118.43)
PB0: length 148.5
  TOP w0.127: U7.27 63.81,95.74 65.48,97.41 65.48,106.08 67.82,108.42 67.82,111.12 67.07,111.87 67.07,115.96 68.45,117.35 89.07,117.35 91.37,119.65 v1(93.06,119.65) ; CN1.34 43.81,160.91 C3.2 43.81,159.47 44.53,158.76 44.53,156.36 45.47,155.42 53.44,155.42 54.08,154.79 89.84,154.79 95.66,148.97 95.66,144.63 CN5.9
  BOTTOM w0.127: CN5.9 94.77,138.46 94.77,121.36 v1(93.06,119.65)
PB1: length 110.9
  TOP w0.127: U7.28 63.35,96.24 65.02,97.92 65.02,106.16 67.44,108.58 67.44,110.67 66.29,111.81 v1(66.29,114.43)
  BOTTOM w0.127: v1(66.29,114.43) 65.15,115.57 55.85,115.57 47.9,123.52 47.9,128.71 37.17,139.45 CN4.10 34.34,141.43 34.34,162.43 35.46,163.55 44.22,163.55 44.96,162.81 50.04,162.81 50.8,163.58 50.8,165.35 CN1.29
PB2: length 178
  TOP w0.127: SB43.1 v1(90.93,17.14) ; v1(66.67,108.71) 64.39,106.43 64.39,98.42 v1(64.07,98.11) 62.7,96.74 U7.29 ; SB17.1 v1(56.01,79.88) ; v1(69.09,93.6) 69.09,93.46 63.25,87.62 63.25,82.42 v1(63.37,82.3)
  BOTTOM w0.127: v1(63.37,82.3) 58.42,82.3 v1(56.01,79.88) ; v1(69.09,93.6) 64.58,98.11 v1(64.07,98.11) ; v1(90.93,17.14) 88.14,17.14 83.82,21.46 83.82,25.27 83.19,25.91 83.19,27.18 84.52,28.51 84.52,30.1 84.84,30.42 84.84,46.23 87.63,49.02 87.63,53.59 91.44,57.4 91.44,62.61 93.47,64.64 94.11,64.64 95.12,65.66 95.12,68.93 98.4,72.21 98.4,97.71 93.22,102.9 93.22,105.41 91.69,106.93 CN10.2 86.69,111.05 69.01,111.05 v1(66.67,108.71)
PB3: length 98.4
  TOP w0.127: SB25.1 90.55,64.64 v1(90.55,64.14) ; R38.2 v1(46.23,95.76)
  BOTTOM w0.127: v1(46.23,95.76) 46.61,96.14 61.47,96.14 68.35,89.26 77.27,89.26 80.64,92.63 80.64,98.42 83.11,100.89 88.93,100.89 90.5,99.31 CN10.8 91.59,99.31 95.07,95.83 95.07,72.37 91.57,68.87 91.57,65.15 v1(90.55,64.14)
PB4: length 101.9
  TOP w0.127: SB12.1 93.6,106.93 93.34,106.68 93.34,96.65 v1(94.08,95.91) ; v1(50.93,93.73) 50.67,93.73 50.66,93.74 U7.58
  BOTTOM w0.127: CN9.14 26.04,91.69 28.45,89.28 44.45,89.28 46.86,91.69 48.9,91.69 v1(50.93,93.73) 63.25,93.73 68.1,88.87 77.83,88.87 81.33,92.38 81.33,98.35 83.24,100.25 88.65,100.25 89.43,99.47 89.43,98.88 90.09,98.22 91.77,98.22 v1(94.08,95.91)
PB5: length 194.7
  TOP w0.127: C2.2 42.55,162.18 CN1.33 50.67,170.31 87.43,170.31 91.59,166.14 99.49,166.14 101.04,164.59 101.04,138.76 99.82,137.54 98.93,137.54 CN5.11 98.3,136.25 99.54,135 99.54,133.43 99.24,133.12 97.82,133.12 97.1,132.41 97.1,126.19 97.69,125.6 99.22,125.6 99.69,125.13 99.69,123.19 99.19,122.68 81.66,122.68 79.88,120.9 59.02,120.9 44.07,105.95 44.07,93.73 44.56,93.24 U7.59
PB6: length 114.2
  TOP w0.127: v1(56.59,119.33) 56.59,119.02 43.69,106.12 43.69,93.47 44.42,92.74 U7.60 ; CN2.3 14.85,154.04 R10.1 15.75,153.16 36.83,153.16 37.47,153.8 37.47,156.08 CN4.3
  BOTTOM w0.127: CN4.3 39.88,153.67 39.88,140.97 50.19,130.66 50.19,125.23 55.91,119.51 56.41,119.51 v1(56.59,119.33)
PB7: length 107.4
  TOP w0.127: U7.61 44.29,92.24 43.31,93.22 43.31,106.55 v1(55.7,118.95) ; CN4.4 20.95,154.69 18.16,157.48 15.75,157.48 R9.1 14.85,156.58 CN2.1
  BOTTOM w0.127: v1(55.7,118.95) 49.81,124.84 49.81,130.4 38.99,141.22 38.99,152.02 CN4.4
PB8: length 96.7
  TOP w0.127: SB27.1 v1(89.92,59.94) ; U7.62 v1(51.01,91.74)
  BOTTOM w0.127: v1(89.92,59.94) 89.92,64.26 91.19,65.53 91.19,69.03 94.69,72.53 94.69,94.41 91.36,97.74 89.84,97.74 CN10.7 83.06,99.31 81.92,98.17 81.92,92.08 78.23,88.39 67.94,88.39 63.25,93.09 52.36,93.09 v1(51.01,91.74)
PB9: length 169.6
  TOP w0.127: U7.63 44.4,91.24 42.8,92.84 42.8,106.81 56.07,120.08 57.34,120.08 58.55,121.28 79.38,121.28 81.15,123.06 98.93,123.06 99.31,123.44 99.31,124.97 99.06,125.22 97.54,125.22 96.57,126.19 96.57,139.34 97.92,140.69 98.88,140.69 99.57,141.38 99.57,145.8 CN5.7 99.77,148.54 99.77,157.78 99.03,158.52 97.87,158.52 95.96,160.43 84.86,160.43 83.9,161.39 83.9,167.16 83.06,168 63.6,168 CN1.21
PB10: length 132.8
  TOP w0.127: v1(60.4,156.59) 62.87,156.59 C7.2 R4.1 ; v1(63.65,114.5) 64.62,113.54 64.62,111 63.75,110.13 63.75,98.9 62.09,97.24 U7.30
  BOTTOM w0.127: v1(63.65,114.5) 53.67,114.5 44.81,123.37 44.81,128.42 CN4.11 32.89,140.34 32.89,163.4 34.95,165.46 42.75,165.46 45.29,168 54.97,168 55.73,167.23 55.73,157.91 57.05,156.59 v1(60.4,156.59)
PB11: length 53.4
  TOP w0.127: U7.31 62.05,97.74 63.37,99.06 63.37,100.86 62.74,101.5 62.74,111.61 v1(63.09,111.96) ; v1(39.62,125.6) R26.2 CN4.15
  BOTTOM w0.127: v1(39.62,125.6) 39.62,119.18 46.84,111.96 v1(63.09,111.96)
PB12: length 84.9
  TOP w0.127: U7.32 61.79,98.24 62.99,99.44 62.99,100.53 62.28,101.24 62.28,111.96 63.04,112.73 v1(63.09,112.73)
  BOTTOM w0.127: JP3.2 30.84,151.03 30.84,136.47 35.48,131.83 CN4.13 38.2,129.95 38.2,128.42 40.39,126.24 40.39,122.38 50.04,112.73 v1(63.09,112.73)
PB13: length 61
  TOP w0.127: v1(63.37,116.46) 61.47,114.55 61.47,103.5 59,101.03 U7.33
  BOTTOM w0.127: CN4.8 37.72,143.13 37.72,140.97 49.05,129.64 49.05,124.21 56.16,117.09 62.74,117.09 v1(63.37,116.46)
PB14: length 57.9
  TOP w0.127: U7.34 58.49,101.29 61.09,103.89 61.09,115.06 v1(62.55,116.52)
  BOTTOM w0.127: CN4.9 36.32,141.73 48.67,129.39 48.67,123.95 56.1,116.52 v1(62.55,116.52)
PB15: length 138.2
  TOP w0.127: v1(88.01,118.9) 86.84,117.73 62.99,117.73 60.58,115.32 60.58,104.01 58,101.43 U7.35 ; CN5.2 99.82,161.29 99.82,163.53 99.01,164.34 90.68,164.34 89.66,165.35 87,165.35 86.23,166.12 86.23,167.39 85.09,168.53 61.59,168.53 CN1.23
  BOTTOM w0.127: v1(88.01,118.9) 88.01,149.48 CN5.2
PC0: length 192.3
  TOP w0.127: CN2.4 3.95,154.04 4.57,153.42 4.57,147.7 5.71,146.56 R12.1 8.26,145.67 41.78,145.67 49.53,153.42 79.25,153.42 v1(80.14,152.53) ; CN10.12 89.66,95.38 87.25,95.38 85.72,96.9 85.72,97.28 84.2,98.81 84.2,114.55 v1(83.82,114.94) ; U7.13 57.49,87.03 v1(57.53,87)
  BOTTOM w0.127: v1(80.14,152.53) 83.68,148.98 83.68,115.07 v1(83.82,114.94) ; CN10.12 90.25,94.23 89.23,95.25 86.74,95.25 78.49,87 67.06,87 65.79,88.27 58.8,88.27 v1(57.53,87)
PC1: length 173.9
  TOP w0.127: v1(93.03,118.74) 90.02,115.72 72.54,115.72 70.23,113.41 70.23,95.5 61.22,86.49 58.55,86.49 58.17,86.87 58.17,87.21 58,87.38 U7.14 ; SB2.1 49.63,159.03 49.63,161.39 50.8,162.56 50.8,164.72 51.44,165.35 52.45,165.35 53.34,166.24 53.34,168.28 54.86,169.8 86.87,169.8 91.01,165.66 99.26,165.66 100.38,164.54 100.38,139.34 99.34,138.3 97.92,138.3 97.28,137.67 97.28,135.38 CN5.12
  BOTTOM w0.127: CN5.12 95.58,131.65 95.58,121.28 v1(93.03,118.74)
PC2: length 115.3
  TOP w0.127: SB41.1 83.19,25.78 81.92,27.05 v1(81.79,27.05) ; v1(58.8,87.12) 58.49,87.43 U7.15
  BOTTOM w0.127: v1(58.8,87.12) 59.56,87.88 65.53,87.88 66.9,86.51 78.89,86.51 86.61,94.23 CN10.11 89.03,94.23 90.3,92.96 91.44,92.96 93.01,91.39 93.01,71.93 90.4,69.32 90.4,66.01 88.93,64.54 88.93,58.83 83.69,53.59 83.69,30.86 83.31,30.48 83.31,29.08 81.79,27.56 v1(81.79,27.05)
PC3: length 120.5
  TOP w0.127: v1(73.53,26.42) 72.39,25.27 71.37,25.27 70.48,24.38 SB37.1 ; v1(59.69,87.12) 59,87.82 U7.16
  BOTTOM w0.127: v1(59.69,87.12) 59.82,87.25 65.53,87.25 66.8,85.98 79.1,85.98 86.26,93.14 89.36,93.14 CN10.14 92.56,89.94 92.56,72.08 89.94,69.46 89.94,66.19 88.47,64.72 88.47,59.13 83.24,53.9 83.24,30.99 82.87,30.62 82.87,29.27 80.64,27.05 74.17,27.05 v1(73.53,26.42)
PC4: length 44.6
  TOP w0.127: v1(59.56,94.74) 59.57,94.74 U7.25
  BOTTOM w0.127: CN9.13 20.68,92.68 27.46,92.68 JP10.1 31.31,92.01 43.75,92.01 44.7,92.96 47.75,92.96 49.53,94.74 v1(59.56,94.74)
PC5: length 41.8
  TOP w0.127: v1(59.56,95.63) 59.96,95.24 U7.26
  BOTTOM w0.127: v1(59.56,95.63) 59.44,95.76 49.15,95.76 47.5,94.11 43.69,94.11 41.27,96.52 30.73,96.52 JP8.1 28.45,94.23 CN9.12
PC6: length 99.6
  TOP w0.127: v1(61.18,117.89) 61.18,117.82 59.31,115.95 59.31,104.52 56.49,101.71 U7.38 ; CN1.31 48.26,165.35 48.26,162.94 46.86,161.54 C1.2 v1(47.75,159.51) SB1.2
  BOTTOM w0.127: v1(47.75,159.51) 47.24,159 40.64,159 38.61,161.04 35.89,161.04 35.36,160.5 35.36,148.03 CN4.7 38.35,145.03 38.35,141.1 49.43,130.02 49.43,124.43 56.13,117.73 61.09,117.73 61.18,117.82 v1(61.18,117.89)
PC7: length 188.4
  TOP w0.127: SB40.1 v1(80.14,23.7) ; U7.39 v1(56,104.38)
  BOTTOM w0.127: v1(80.14,23.7) 72.57,16.13 55.16,16.13 48.77,22.52 48.77,50.29 45.47,53.59 27.52,53.59 23.11,58 23.11,61.3 20.87,63.54 18.2,63.54 16.38,65.36 16.38,101.09 CN9.3 20.83,105.54 54.84,105.54 v1(56,104.38)
PC8: length 174.9
  TOP w0.127: SB39.1 v1(76.96,23.7) ; U7.48 51.49,101.67 v1(51.31,101.85)
  BOTTOM w0.127: v1(51.31,101.85) CN9.6 21.46,101.85 20.32,100.71 17.78,100.71 17.4,100.33 17.4,65.79 18.63,64.56 21.29,64.56 24.13,61.72 24.13,58.42 28.19,54.36 46.32,54.36 49.28,51.4 49.28,22.73 55.37,16.64 72.36,16.64 76.96,21.24 v1(76.96,23.7)
PC9: length 112.9
  TOP w0.127: SB8.1 87.35,113.41 84.99,111.05 v1(84.99,102.08) ; U7.49 48.57,98.24 v1(47.88,98.93)
  BOTTOM w0.127: CN9.7 20.95,100.58 46.23,100.58 v1(47.88,98.93) 49.71,98.93 50.98,100.2 59.44,100.2 68.07,91.57 77.72,91.57 79.5,93.34 79.5,98.55 83.03,102.08 v1(84.99,102.08)
PC10: length 98.5
  TOP w0.127: v1(57.02,120.9) 56.71,120.59 55.82,120.59 42.29,107.06 42.29,92.58 44.14,90.74 v1(47.68,90.74) U7.64 ; v1(56.01,141.35) SB5.2
  BOTTOM w0.127: v1(57.02,120.9) 56.39,120.9 53.47,123.83 53.47,134.11 57.53,138.18 57.53,139.06 55.97,140.63 55.97,141.31 v1(56.01,141.35) ; CN9.15 20.89,90.36 25.97,90.36 27.56,88.77 45.72,88.77 v1(47.68,90.74)
PC11: length 51.7
  TOP w0.127: CN9.16 20.83,90.55 18.8,90.55 12.62,96.72 7.67,96.72 JP7.1 ; U7.1 51.49,87.31 v1(51.37,87.19)
  BOTTOM w0.127: v1(51.37,87.19) 50.67,87.88 27.05,87.88 25.78,89.15 CN9.16
PC12: length 75
  TOP w0.127: v1(52.1,89.99) 52,89.89 U7.2 ; SB26.1 v1(89.41,66.57)
  BOTTOM w0.127: v1(89.41,66.57) 88.77,67.21 88.77,69.22 89.15,69.6 89.53,69.6 92.13,72.19 92.13,88.85 91.82,89.15 CN10.16 89.66,88.01 85.85,88.01 79.63,81.79 67.82,81.79 65.28,84.33 58.61,84.33 57.47,85.47 54.05,85.47 52.1,87.43 v1(52.1,89.99)
PC13: length 84.3
  TOP w0.127: U7.3 52.49,87.42 46.74,81.66 v1(46.74,80.77) R47.2 ; SB42.1 v1(59.05,17.4)
  BOTTOM w0.127: v1(46.74,80.77) 46.74,79.88 45.72,78.87 45.72,65.53 50.04,61.21 50.04,27.69 51.82,25.91 51.82,20.73 55.15,17.4 v1(59.05,17.4)
PC14: length 8.5
  TOP w0.127: U7.4 53,87.16 50.42,84.58 R43.2 SB18.1
PC15: length 8.2
  TOP w0.127: SB19.2 R44.2 51.69,85.09 53.49,86.9 U7.5
PD0: length 167.8
  TOP w0.127: CN1.27 53.34,165.35 53.34,163.58 50.67,160.91 SB2.2 C4.2 52.07,159.47 52.76,158.79 52.76,157.4 54.53,155.63 89.92,155.63 v1(94.59,150.95) ; U7.50 48.19,97.74 45.85,100.08 45.85,105.35 59.75,119.25 81.28,119.25 82.33,120.31 94.58,120.31 96.9,117.98 98.93,117.98 101.6,120.65 101.6,128.52 CN5.13
  BOTTOM w0.127: v1(94.59,150.95) 99.19,150.95 99.64,150.5 99.64,133.17 CN5.13
PD1: length 94.4
  TOP w0.127: SB9.1 86.74,108.46 86.21,107.92 v1(86.21,102.08) ; U7.51 47.8,97.24 v1(47.24,97.79)
  BOTTOM w0.127: CN9.8 45.72,99.31 v1(47.24,97.79) 49.38,97.79 51.28,99.69 59.18,99.69 67.94,90.93 77.98,90.93 79.95,92.9 79.95,98.36 83.13,101.55 85.67,101.55 v1(86.21,102.08)
PD2: length 140
  TOP w0.127: U7.52 47.41,96.74 45.21,98.93 45.21,105.28 59.63,119.7 80.92,119.7 81.92,120.69 95.21,120.69 95.63,120.27 99.82,120.27 100.84,121.28 100.84,127.64 99.19,129.29 CN5.14
  BOTTOM w0.127: CN5.14 99.57,129.29 100.46,130.18 100.46,163.19 95.11,168.53 84.45,168.53 CN1.5
PD3: length 146.7
  TOP w0.127: CN5.15 99.82,126.75 100.2,126.36 100.2,121.28 99.57,120.65 96.14,120.65 95.72,121.07 81.76,121.07 80.83,120.14 59.44,120.14 44.83,105.54 44.83,98.68 47.27,96.24 U7.53
  BOTTOM w0.127: CN5.15 101.09,129.54 101.09,163.45 95.38,169.16 80.01,169.16 CN1.9
PD4: length 136.2
  TOP w0.127: v1(89.53,121.64) 81.28,121.64 80.16,120.52 59.18,120.52 44.45,105.79 44.45,98.42 47.14,95.74 U7.54 ; CN5.6 98.3,150.52 97.28,151.54 97.28,153.37 91.92,158.72 80.98,158.72 78.41,161.29 75.69,161.29 73.66,163.32 73.66,165.35 CN1.13
  BOTTOM w0.127: v1(89.53,121.64) 89.53,121.79 89.28,122.05 89.28,146.69 92.2,149.61 CN5.6
PD5: length 140
  TOP w0.127: SB36.2 27.97,27.79 27.97,56.31 25.45,58.83 25.45,62.69 23.62,64.52 18.67,64.52 13.21,69.98 6.99,69.98 3.96,73 3.96,99.87 4.65,100.56 15.9,100.56 CN9.9 ; U7.55 v1(47.87,95.24)
  BOTTOM w0.127: v1(47.87,95.24) 44.08,95.24 41.27,98.04 20.95,98.04 CN9.9
PD6: length 145.4
  TOP w0.127: U7.56 v1(47.12,94.74) ; SB35.2 27.51,26.59 27.51,56.12 24.99,58.64 24.99,62.5 23.43,64.06 18.48,64.06 13.02,69.52 6.8,69.52 3.51,72.81 3.51,100.05 4.52,101.07 16.28,101.07 19.38,97.97 20.07,97.97 20.85,97.18 20.85,95.4 CN9.11
  BOTTOM w0.127: CN9.11 20.95,95.5 24.26,95.5 25.91,97.16 41.27,97.16 43.69,94.74 v1(47.12,94.74)
PD8: length 152.6
  TOP w0.127: CN9.1 17.37,104.62 4.65,104.62 2.97,102.95 2.97,72.66 6.6,69.04 12.82,69.04 18.28,63.58 23.23,63.58 24.51,62.3 24.51,58.44 27.03,55.92 27.03,26.64 SB34.2 ; SB11.2 v1(58.42,107.44)
  BOTTOM w0.127: v1(58.42,107.44) 57.53,108.33 21.08,108.33 CN9.1
PD9: length 147.2
  TOP w0.127: SB33.2 26.57,27.84 26.57,55.73 24.05,58.25 24.05,62.11 23.04,63.12 18.09,63.12 12.63,68.58 6.41,68.58 2.51,72.47 2.51,103.25 4.34,105.08 16.24,105.08 18.95,107.78 21.37,107.78 CN9.2 ; SB10.2 v1(51.82,107.44)
  BOTTOM w0.127: CN9.2 22.73,107.44 v1(51.82,107.44)
PF0: length 11.3
  TOP w0.127: SB20.1 58.93,82.3 R45.2 59.69,83.19 59.69,84.84 59.18,85.34 57.15,85.34 56.13,86.36 56.13,87.45 56.11,87.47 56.11,87.52 56,87.64 U7.10
PF1: length 11
  TOP w0.127: SB21.1 61.59,81.03 R46.2 60.2,84.96 59.44,85.72 57.4,85.72 56.61,86.51 56.61,87.51 56.49,87.63 U7.11
PF2: length 37.1
  TOP w0.127: v1(63.88,85.34) 64.01,85.22 64.01,81.28 SB23.2 62.61,81.66 62.61,84.45 60.96,86.11 57.66,86.11 57,86.77 U7.12 ; v1(79.76,83.69) 81.28,83.69 R41.1
  BOTTOM w0.127: v1(79.76,83.69) 78.99,82.93 68.2,82.93 65.79,85.34 v1(63.88,85.34)
PF3: length 54.8
  TOP w0.127: v1(53.72,84.84) 53.59,84.96 53.59,86.36 54,86.76 U7.6
  BOTTOM w0.127: JP15.2 46.23,70.36 46.23,78.61 52.32,84.71 53.59,84.71 v1(53.72,84.84) 57.56,84.84 58.45,83.95 64.77,83.95 67.31,81.41 80.01,81.41 81.53,82.93 SB44.2
PF4: length 41.4
  TOP w0.127: U7.7 54.49,86.37 v1(54.23,86.11) 54.23,85.48 54.49,85.22 54.49,83.83 54.48,83.82 SB22.2 SB17.2 54.48,78.49 TP4.1
  BOTTOM w0.127: v1(54.23,86.11) 53.72,86.61 C38.2 ; SB45.2 81.79,81.03 62.1,81.03 61.09,80.01 57.66,80.01 56.9,79.25 55.5,79.25 TP4.1
PWR_ENN: length 58.9
  TOP w0.127: U2.28 52.85,137.9 52.2,138.56 29.44,138.56 v1(29.21,138.79) ; U5.4 23.11,118.37 R32.2 21.97,115.95 v1(21.84,116.08)
  BOTTOM w0.127: v1(21.84,116.08) 21.84,122.05 23.94,124.14 23.94,125.29 29.21,130.56 v1(29.21,138.79)
RESET#: length 339.6
  TOP w0.127: v1(83.82,27.05) 83.06,27.05 82.42,27.69 80.26,27.69 79.63,27.05 72.26,27.05 64.9,19.68 v1(53.72,19.68) 48.77,14.73 C88.2 42.55,10.04 B1.2 B1.3 ; v1(79.38,152.53) 78.87,153.03 64.39,153.03 63.63,152.27 63.63,143 v1(62.74,142.11) 62.73,142.11 U2.18 ; R11.1 v1(42.42,149.61) ; T2.2 v1(93.22,55.06) ; v1(100.46,71.37) 100.33,71.5 R54.2 ; SB23.1 D5.1 62.74,76.56 62.74,75.06 60.71,73.03 v1(52.7,73.03)
  BOTTOM w0.127: v1(79.38,152.53) 83.17,148.73 83.17,114.06 84.71,112.52 96.65,112.52 101.6,107.57 101.6,101.98 100.46,100.84 v1(100.46,71.37) 100.46,68.33 98.04,65.91 98.04,64.52 95.38,61.85 95.38,57.22 v1(93.22,55.06) 93.22,52.96 91.06,50.8 90.42,50.8 85.47,45.85 85.47,30.61 85.85,30.23 85.85,28.83 85.47,28.45 85.47,27.56 84.96,27.05 v1(83.82,27.05) ; v1(62.74,142.11) 61.85,143 61.85,146.05 58.29,149.61 v1(42.42,149.61) ; v1(53.72,19.68) 52.7,20.7 v1(52.7,73.03)
SPI1_MOSI_3V3: length 66.7
  TOP w0.178: v1(97.66,104.01) 97.61,103.96 U6.5
  TOP w0.254: v1(86.87,67.18) 86.62,67.43 U10.7 ; v1(94.11,57.53) 93.98,57.66 92.96,57.66 R63.2 88.77,58.42 v1(87,60.2)
  BOTTOM w0.254: v1(86.87,67.18) 86.87,60.33 v1(87,60.2) ; v1(94.11,57.53) 94.55,57.98 94.55,62.29 95.89,63.63 95.89,68.71 99.1,71.92 99.1,103.09 98.17,104.01 v1(97.66,104.01)
SPI1_SCK_3V3: length 52.5
  TOP w0.127: U6.6 96.73,104.38 97.17,104.38 97.54,104.74 97.54,104.78 97.66,104.9 v1(97.66,105.22) ; CN14.2 99.57,61.47 99.57,66.8 99.31,67.06 v1(97.54,67.06) 96.65,67.06 96.27,67.43 U11.7
  BOTTOM w0.127: v1(97.66,105.22) 98.64,105.22 99.95,103.92 99.95,76.45 99.92,76.43 99.92,69.44 v1(97.54,67.06)
STL_USB_DM: length 54.7
  TOP w0.155: U2.32 57.21,135.9 57.15,135.84 12.37,135.84 11.5,136.71 U3.6 U3.1 6.78,136.71 6.1,136.02 5.11,136.02 4.98,136.16 CN6.2
STL_USB_DP: length 54.7
  TOP w0.155: CN6.3 4.98,135.51 5.11,135.64 5.96,135.64 6.79,134.81 U3.3 U3.4 11.62,134.81 R18.1 12.27,135.46 57.15,135.46 57.21,135.4 U2.33
STLINK_RX: length 10.1
  TOP w0.127: CN3.1 65.02,150.95 SB3.2 65.02,142.7 65.23,142.49 U2.13
STLINK_TX: length 119.7
  TOP w0.127: CN3.2 67.64,142.57 66.83,141.76 U2.12 ; v1(52.58,154.43) 49.78,154.43 41.53,146.18 30,146.18 v1(29.62,146.56)
  BOTTOM w0.127: CN3.2 64.24,154.43 v1(52.58,154.43) ; JP7.2 18.92,109.09 28.96,109.09 32.13,112.27 32.13,133.73 29.82,136.04 29.82,146.35 v1(29.62,146.56)
STLK_RX: length 21.2
  TOP w0.127: SB3.1 v1(66.55,142.37) ; U1.3 49.28,141.86 v1(49.66,142.24)
  BOTTOM w0.127: v1(66.55,142.37) 65.02,140.84 58.93,140.84 56.52,143.26 50.67,143.26 v1(49.66,142.24)
STM_JTCK_SWCLK: length 7.1
  TOP w0.127: CN7.3 59.73,127.81 U2.37
STM_JTMS_SWDIO: length 14.2
  TOP w0.127: CN7.1 53.09,128.27 53.09,133.73 54.26,134.9 U2.34
STM_RST: length 7
  TOP w0.127: 72.64,139.83 SB6.2 C16.2 R17.1 67.81,136.9 U2.7
T_JTCK: length 138
  TOP w0.127: v1(82.68,115.06) 83.44,114.3 83.44,98.63 v1(82.68,97.87) 79.3,94.49 73.41,94.49 JP9.1 ; v1(78.58,152.51) 78.56,152.53 64.64,152.53 64.06,151.95 64.06,141.17 U2.15 64.23,139.93 63.21,138.9 U2.26 ; R50.2 v1(94.11,73.41)
  BOTTOM w0.127: v1(78.58,152.51) 82.68,148.41 v1(82.68,115.06) ; v1(82.68,97.87) 88.9,97.87 89.48,97.28 89.48,96.6 90.32,95.76 92.43,95.76 94.11,94.08 v1(94.11,73.41)
T_SWDIO_IN: length 13.7
  TOP w0.127: U2.25 48.43,139.4 47.75,140.08 47.75,142.11 48,142.36 U1.2
U5V_ST_LINK: length 97
  TOP w0.508: 24.64,122.48 C25.2 ; C25.2 25.26,123.06 ; C25.2 24.64,123.65 ; U5.1 24.95,121.85
  BOTTOM w1.016: v1(25.65,125.09) v1(25.65,124.21) 25.65,116.71 23.52,114.58 18.44,114.58 11.23,107.37 7.04,107.37 3.3,103.63 3.3,60.83 6.1,58.04 10.92,58.04 12.32,56.64 12.32,54.86 JP17.2
USART1_RTS_3V3: length 47.4
  TOP w0.254: 33.78,82.67 U8.6
  TOP w0.356: 33.4,53.72 33.77,54.09 U13.14 37.3,54.09
  TOP w0.508: 37.3,54.09 38.71,55.5 38.71,64.29 34.42,68.58 34.42,82.03 33.78,82.67 ; U15.3 34.01,48.92 R81.2 ; 33.4,53.72 32.26,52.58 32.26,50.04 32.77,49.53 R81.2 ; R81.2 34.06,50.19 U15.2
USART1_TX_3V3: length 45.2
  TOP w0.254: U8.7 33.27,82.17 33.53,81.92 33.53,81.66
  TOP w0.356: 36.94,55.13 36.55,54.74 U13.13 33.66,54.74 33.66,54.74 33.02,54.74 32.77,54.48
  TOP w0.508: 32.77,54.48 31.37,53.09 31.37,49.53 33.25,47.65 U15.4 ; 36.94,55.13 37.82,56.01 37.82,63.78 33.53,68.07 33.53,81.66
USB_RENUMN: length 56.1
  TOP w0.127: R22.2 21.46,131.32 22.1,130.68 44.96,130.68 50.93,124.71 61.21,124.71 61.72,125.22 61.72,129.29 60.23,130.77 U2.38
VREF+: length 24.9
  TOP w0.508: v1(65.41,81.79) 65.41,78.61 67.18,76.83 C39.1 70.1,78.23 73.03,78.23 L1.2 ; SB22.1 v1(56.01,83.82)
  BOTTOM w0.508: v1(56.01,83.82) 57.28,83.82 57.78,83.31 64.52,83.31 65.41,82.42 v1(65.41,81.79)
VUSB_ST_LINK: length 116.7
  TOP w0.381: 5.11,136.81 CN6.1
  TOP w0.508: R21.2 v1(14.86,132.33) ; C28.1 28.5,117.47 ; C28.1 26.62,117.47 ; C28.1 27.56,116.66 ; C28.1 27.56,118.29 ; U3.5 v1(10.79,135.76) ; 24.64,115.37 R32.1 ; R32.1 25.21,115.95 ; R32.1 24.64,116.54 ; 24.95,117.68 U5.5 ; U5.5 24.46,118.43 ; U5.5 25.45,118.43 ; 18.41,114.81 6.99,114.81 R33.1 ; D2.1 39.62,117.47 38.35,116.2 29.34,116.2 ; v1(7.75,139.57) C17.2 6.73,138.43 5.11,136.81 ; R31.1 19.81,119.13
  BOTTOM w1.016: v1(19.24,117.54) v1(18.54,116.84) 10.9,109.19 6.5,109.19 1.4,104.09 1.4,54.36 JP17.8
  vias: v1(18.29,124.71) v1(18.41,125.6) v1(19.05,125.09)

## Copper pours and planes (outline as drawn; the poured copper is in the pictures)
+3V3 on TOP (solid shape): 64.39,37.63 63.88,38.13 63.37,37.62 63.37,38.99 64.39,38.99
+3V3 on TOP (solid shape): 66.17,37.63 65.66,38.13 65.15,37.62 65.15,38.99 66.17,38.99
+3V3 on TOP: 61.85,48.77 64.39,48.77 66.8,46.35 66.8,40.13 66.04,39.37 65.15,39.37 64.77,39.75 64.77,43.05 64.39,43.43 62.36,43.43 61.98,43.81 61.34,43.81 61.21,43.94 61.21,48.13
+3V3 on L2_VCC: outline of 108 points within 0.51,0.51 102.36,164.97
+3V3_SD on TOP (solid shape): 64.39,37.37 64.39,36.45 63.37,36.45 63.37,37.37 63.88,37.88
+3V3_SD on TOP (solid shape): 66.17,37.37 66.17,36.45 65.15,36.45 65.15,37.37 65.66,37.88
+3V3_SD on TOP (solid shape): 96.01,99.6 96.01,98.68 95,98.68 95,99.6 95.5,100.11
+3V3_SD on TOP: 64.01,31.37 62.48,31.37 62.23,31.62 61.21,31.62 60.96,31.88 60.96,35.94 61.34,36.32 66.42,36.32 66.42,32.64 68.33,30.73 75.31,30.73 77.6,33.02 90.04,33.02 93.47,36.45 99.57,36.45 100.33,35.69 100.33,34.67 99.69,34.04 95.76,34.04 92.33,30.61 79.76,30.61 77.47,28.32 66.55,28.32 64.77,30.1 64.77,30.61
+3V3_SD on L2_VCC: 94.36,110.59 100.51,110.59 101.09,110.01 101.09,70.26 102.36,68.99 102.36,35.2 101.47,34.32 95.86,34.32 94.92,35.26 94.92,62.87 95.17,63.12 97.51,63.12 98.27,63.88 98.27,66.42 96.65,68.05 96.65,70 98.04,71.4 98.04,83.77 93.19,88.62 93.19,109.42
+3V3_ST_LINK on TOP: 42.04,124.21 45.97,124.21 46.1,124.08 46.1,121.03 45.85,120.78 42.04,120.78 41.78,121.03 41.78,123.95
+3V3_ST_LINK on L2_VCC: 41.78,120.78 41.78,128.93 43.54,130.68 51.29,130.68 52.58,131.97 52.58,134.13 53.19,134.75 58.78,134.75 59.44,135.4 59.44,139.7 57.28,141.86 57.28,144.65 57.78,145.16 67.33,145.16 68.98,143.51 74.57,143.51 75.31,142.77 75.31,132.95 73.3,130.94 66.44,130.94 65.53,130.03 65.53,129.52 65.43,129.41 62.89,129.41 62.23,128.76 62.23,124.18 61.87,123.83 55.39,123.83 52.35,120.78
+5V on TOP: 59.18,45.21 59.69,44.7 59.69,43.81 58.67,43.81 57.78,42.93 54.86,42.93 54.61,43.18 54.61,45.09 54.74,45.21
+5V on TOP: 55.37,56.77 58.93,56.77 59.44,56.26 59.44,55.24 58.42,55.24 57.91,54.74 55.37,54.74 54.99,55.12 54.99,56.39
+5V on TOP: 54.36,31.62 54.61,31.37 57.78,31.37 58.04,31.62 59.56,31.62 59.56,32.64 59.44,32.77 56.77,32.77 56.26,33.27 56.26,36.32 55.88,36.7 54.61,36.7 54.36,36.45
+5V on TOP: 1.52,60.58 13.59,60.58 14.61,59.56 14.61,58.29 13.72,57.4 13.72,55.75 13.59,55.63 11.94,55.63 11.56,55.24 11.56,54.61 11.43,54.48 1.52,54.48 1.27,54.74 1.27,60.33
+5V on L2_VCC: 70.46,29.08 64.75,34.8 34.9,34.8 17.89,51.82 0.51,51.82 0.51,131.47 0.48,131.5 0.48,139.55 0.51,139.57 0.51,172.21 113.79,172.21 113.79,138.56 92.96,138.56 78.36,123.95 69.19,123.95 67.69,125.45 67.69,127.66 68.05,128.02 75.67,128.02 77.98,130.32 77.98,146.16 81.03,149.2 81.03,152.91 78.99,154.94 57.78,154.94 57.4,155.32 57.4,164.95 56.87,165.48 41.68,165.48 40.64,164.44 40.64,153.27 38.38,151 18.69,151 8.26,140.57 8.26,132.61 12.59,128.27 15.52,128.27 16.26,127.53 16.26,81.17 36.2,61.24 36.2,48.41 39.52,45.09 60.35,45.09 60.98,44.45 64.62,44.45 65.41,45.23 65.41,49 64.62,49.78 63.61,49.78 63.37,50.02 63.37,50.78 62.46,51.69 55.22,51.69 54.99,51.92 54.99,56.41 55.6,57.02 87.78,57.02 88.77,56.03 88.77,31.09 86.76,29.08
GND on TOP (solid shape): 58.04,105.03 57.12,105.03 56.61,105.54 57.12,106.05 58.04,106.05
